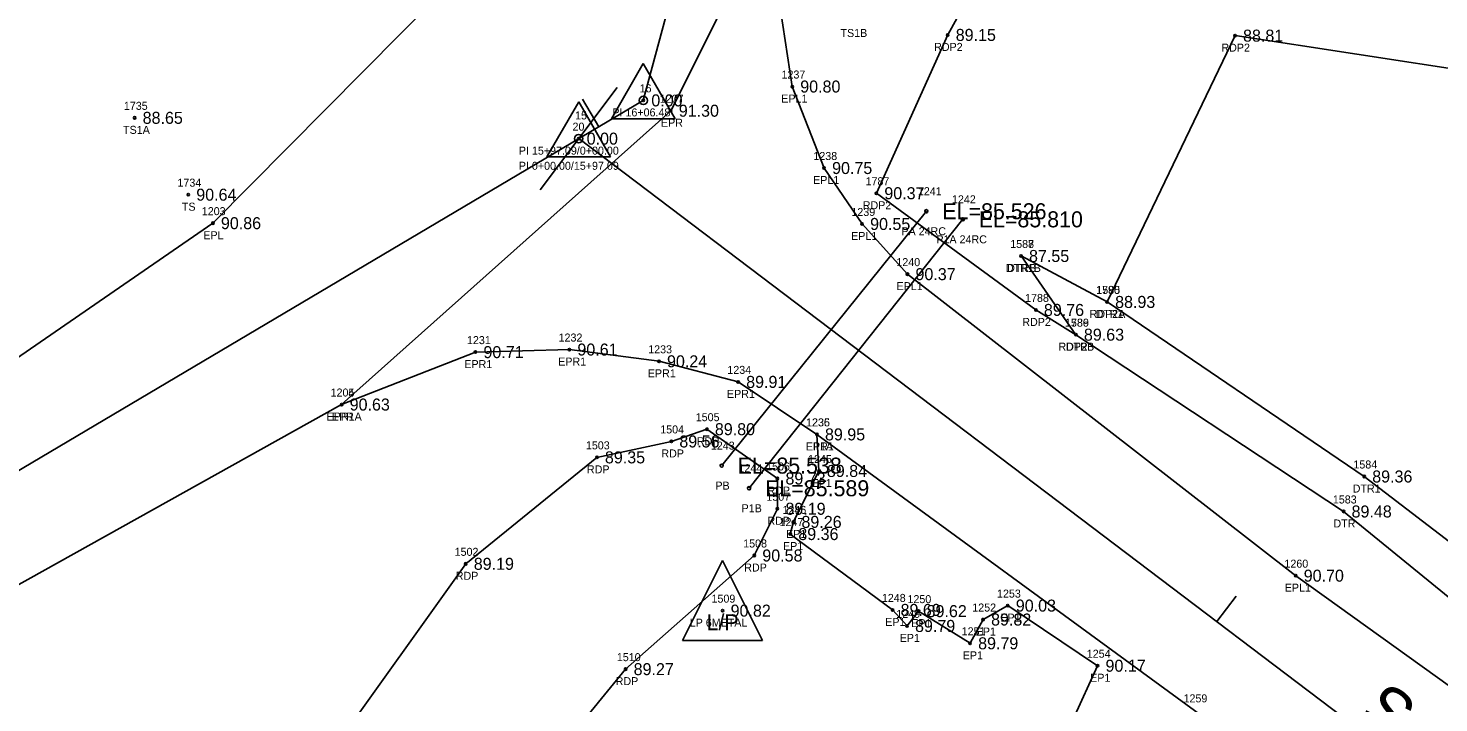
# Model space of a CAD drawing. Extents: x 2529517 to 2532038, y 935000 to 936944.
# Drawn here: x 2531691.2 to 2531867.5, y 936267.3 to 936351.6 of the extents above; entities that cross this region are included whole.
import ezdxf

# ---------------------------------------------------------------- set-up
doc = ezdxf.new("R2010")
doc.units = 0
for name, color, linetype in [('Default', 7, 'Continuous'), ('RD_DTM_BkLn_txCode', 7, 'Continuous'), ('RD_EX_DR_ErosCtrl', 7, 'Continuous'), ('RD_EX_DR_ErosCtrl_txCode', 7, 'Continuous'), ('RD_EX_DR_Pipe', 7, 'Continuous'), ('RD_EX_DR_Pipe_txCode', 7, 'Continuous'), ('RD_EX_H2O', 7, 'Continuous'), ('RD_EX_H2O_txCode', 7, 'Continuous'), ('RD_EX_Road', 7, 'Continuous'), ('RD_EX_Road_txCode', 7, 'Continuous'), ('RD_EX_TX_DR_ErosCtrl_ELEV', 7, 'Continuous'), ('RD_EX_TX_H2O_ELEV', 7, 'Continuous'), ('RD_EX_TX_Misc_ELEV', 7, 'Continuous'), ('RD_EX_TX_Road_ELEV', 7, 'Continuous'), ('RD_EX_TX_UT_ELEV', 7, 'Continuous'), ('RD_EX_UT', 7, 'Continuous'), ('RD_EX_UT_txCode', 7, 'Continuous'), ('RD_HC_Cl', 7, 'Continuous'), ('RD_HC_Data', 7, 'Continuous'), ('RD_HC_Data_Tic', 7, 'Continuous'), ('RD_HC_Survey_ELEV', 7, 'Continuous'), ('RD_HC_txCode', 7, 'Continuous'), ('RD_SMD_Locator', 7, 'Continuous'), ('RD_TX_Pipe_ElevEX', 7, 'Continuous')]:
    doc.layers.add(name, color=color, linetype=linetype)

msp = doc.modelspace()

# ---------------------------------------------------------------- linework, layer by layer
at = {"layer": 'Default'}
for p, q in [((2531768.07, 936342.55), (2531830.33, 936573.34)), ((2530557.05, 935625.34), (2531768.07, 936342.55)), ((2531759.99, 936337.77), (2531999.23, 936156.76))]:
    msp.add_line(p, q, dxfattribs=at)
at = {"layer": 'RD_EX_DR_ErosCtrl'}
for points in [[(2531913.23, 936552.65), (2531879.89, 936486.26), (2531843.11, 936418.02), (2531806.11, 936350.73), (2531797.19, 936330.95), (2531817.13, 936316.37), (2531822.13, 936313.28)], [(2531826.03, 936317.37), (2531842.02, 936350.64), (2531872.46, 936345.98), (2531906.05, 936401.13), (2531944.32, 936458.1), (2531968.34, 936447.83), (2531976.81, 936458.99), (2531957.81, 936476.14), (2531966.51, 936493.14)], [(2531712.5, 936237.97), (2531745.88, 936284.65), (2531762.27, 936297.95), (2531771.57, 936299.94), (2531776.01, 936301.47), (2531784.83, 936295.31), (2531784.83, 936291.53), (2531781.94, 936285.69), (2531765.86, 936271.49), (2531751.65, 936254.14)]]:
    msp.add_lwpolyline(points, dxfattribs=at)
at = {"layer": 'RD_EX_DR_Pipe'}
for p, q in [((2531803.44, 936328.7), (2531777.86, 936296.92)), ((2531807.99, 936327.69), (2531781.29, 936294.09))]:
    msp.add_line(p, q, dxfattribs=at)
at = {"layer": 'RD_EX_H2O'}
for points in [[(2531888.89, 936272.02), (2531858.16, 936295.56), (2531826.03, 936317.37), (2531815.27, 936323.11)], [(2531888.89, 936272.02), (2531887.88, 936268.95), (2531883.72, 936268.22), (2531855.58, 936291.19), (2531822.13, 936313.28), (2531815.27, 936323.11)]]:
    msp.add_lwpolyline(points, dxfattribs=at)
at = {"layer": 'RD_EX_Road'}
for points in [[(2531169.65, 936000.77), (2531208.79, 936024.95), (2531292.04, 936074.02), (2531376.24, 936123.7), (2531460.37, 936174.49), (2531542.92, 936223.44), (2531626.67, 936270.85), (2531672.4, 936298.39), (2531714.28, 936327.21), (2531747.19, 936360.45), (2531761.42, 936377.32), (2531773.11, 936411.11), (2531782.2, 936441.65), (2531803.17, 936514.76), (2531820.28, 936585.8)], [(2531180.82, 935982), (2531220.82, 936004.21), (2531303.54, 936053.39), (2531388.75, 936103.71), (2531472.27, 936152.98), (2531554.79, 936201.9), (2531638.11, 936250.92), (2531683.19, 936278.28), (2531730.37, 936304.55), (2531771.5, 936341.26), (2531788.67, 936375.53), (2531805.57, 936434.84), (2531825.53, 936508.74), (2531844.13, 936579.65)], [(2531788.67, 936375.53), (2531784.05, 936361.55), (2531786.68, 936344.28), (2531790.66, 936334.1), (2531795.41, 936327.11), (2531801.08, 936320.84), (2531849.6, 936283.17), (2531876.01, 936264.22), (2531894.71, 936249.13), (2531930.69, 936221.59), (2532010.91, 936160.51)], [(2531730.37, 936304.55), (2531747.09, 936311.1), (2531758.83, 936311.42), (2531770.03, 936309.95), (2531779.92, 936307.38), (2531789.77, 936300.82), (2531836.93, 936266.34), (2531918.06, 936205.29), (2531926.11, 936199.32), (2531961.6, 936172.59), (2531979.77, 936158.9), (2531999.31, 936144.02)], [(2531789.77, 936300.82), (2531790.01, 936296.25), (2531786.83, 936289.89), (2531786.44, 936288.37), (2531799.22, 936278.89), (2531801.03, 936276.89), (2531802.47, 936278.74), (2531808.91, 936274.72), (2531810.53, 936277.69), (2531813.62, 936279.43), (2531824.83, 936271.92), (2531821.79, 936265.23), (2531839.12, 936251.81), (2531833.01, 936238.75), (2531836.1, 936237.39)]]:
    msp.add_lwpolyline(points, dxfattribs=at)
at = {"layer": 'RD_EX_UT'}
for p, q in [((2531772.98, 936275.08), (2531777.98, 936285.08)), ((2531777.98, 936285.08), (2531782.98, 936275.08)), ((2531772.98, 936275.08), (2531782.98, 936275.08))]:
    msp.add_line(p, q, dxfattribs=at)
at = {"layer": 'RD_HC_Cl'}
for p, q in [((2531768.07, 936342.55), (2531830.33, 936573.34)), ((2530557.05, 935625.34), (2531768.07, 936342.55)), ((2531759.99, 936337.77), (2531999.23, 936156.76))]:
    msp.add_line(p, q, dxfattribs=at)
at = {"layer": 'RD_HC_Data'}
for p, q in [((2531764.1, 936340.26), (2531768.07, 936347.14)), ((2531768.07, 936347.14), (2531772.04, 936340.26)), ((2531756.02, 936335.48), (2531759.99, 936342.36)), ((2531756.02, 936335.48), (2531759.99, 936342.36)), ((2531759.99, 936342.36), (2531763.96, 936335.48)), ((2531759.99, 936342.36), (2531763.96, 936335.48)), ((2531764.1, 936340.26), (2531772.04, 936340.26)), ((2531756.02, 936335.48), (2531763.96, 936335.48)), ((2531756.02, 936335.48), (2531763.96, 936335.48))]:
    msp.add_line(p, q, dxfattribs=at)
for centre in [(2531768.07, 936342.55), (2531759.99, 936337.77), (2531759.99, 936337.77)]:
    msp.add_circle(centre, 0.529, dxfattribs=at)
at = {"layer": 'RD_HC_Data_Tic'}
for p, q in [((2531759.99, 936337.77), (2531764.82, 936344.15)), ((2531762.49, 936339.25), (2531760.46, 936342.69)), ((2531759.99, 936337.77), (2531755.16, 936331.39)), ((2531839.74, 936277.43), (2531842.15, 936280.62))]:
    msp.add_line(p, q, dxfattribs=at)
at = {"layer": 'RD_SMD_Locator'}
for centre, radius in [((2531806.11, 936350.73), 0.15), ((2531842.02, 936350.64), 0.15), ((2531786.68, 936344.28), 0.15), ((2531768.07, 936342.55), 0.15), ((2531704.5, 936340.37), 0.15), ((2531771.5, 936341.26), 0.15), ((2531759.99, 936337.77), 0.15), ((2531759.99, 936337.77), 0.15), ((2531790.66, 936334.1), 0.15), ((2531711.2, 936330.77), 0.15), ((2531797.19, 936330.95), 0.15), ((2531803.44, 936328.7), 0.2), ((2531807.99, 936327.69), 0.2), ((2531714.28, 936327.21), 0.15), ((2531795.41, 936327.11), 0.15), ((2531815.27, 936323.11), 0.15), ((2531815.27, 936323.11), 0.15), ((2531801.08, 936320.84), 0.15), ((2531826.03, 936317.37), 0.15), ((2531826.03, 936317.37), 0.15), ((2531817.13, 936316.37), 0.15), ((2531822.13, 936313.28), 0.15), ((2531822.13, 936313.28), 0.15), ((2531747.09, 936311.1), 0.15), ((2531758.83, 936311.42), 0.15), ((2531770.03, 936309.95), 0.15), ((2531779.92, 936307.38), 0.15), ((2531730.37, 936304.55), 0.15), ((2531730.37, 936304.55), 0.15), ((2531776.01, 936301.47), 0.15), ((2531771.57, 936299.94), 0.15), ((2531789.77, 936300.82), 0.15), ((2531789.77, 936300.82), 0.15), ((2531762.27, 936297.95), 0.15), ((2531777.86, 936296.92), 0.2), ((2531790.01, 936296.25), 0.15), ((2531781.29, 936294.09), 0.2), ((2531784.83, 936295.31), 0.15), ((2531858.16, 936295.56), 0.15), ((2531784.83, 936291.53), 0.15), ((2531855.58, 936291.19), 0.15), ((2531786.83, 936289.89), 0.15), ((2531786.44, 936288.37), 0.15), ((2531781.94, 936285.69), 0.15), ((2531745.88, 936284.65), 0.15), ((2531849.6, 936283.17), 0.15), ((2531777.98, 936278.8), 0.15), ((2531799.22, 936278.89), 0.15), ((2531802.47, 936278.74), 0.15), ((2531813.62, 936279.43), 0.15), ((2531801.03, 936276.89), 0.15), ((2531810.53, 936277.69), 0.15), ((2531808.91, 936274.72), 0.15), ((2531765.86, 936271.49), 0.15), ((2531824.83, 936271.92), 0.15)]:
    msp.add_circle(centre, radius, dxfattribs=at)

# ---------------------------------------------------------------- texts
at = {"layer": 'RD_DTM_BkLn_txCode'}
for s, p in [('TS1B', (2531792.71, 936350.47)), ('1735', (2531703.15, 936341.37)), ('TS1A', (2531703.05, 936338.37)), ('1734', (2531709.85, 936331.77)), ('TS', (2531710.4, 936328.77))]:
    msp.add_text(s, height=1, dxfattribs=at).set_placement(p)
at = {"layer": 'RD_EX_DR_ErosCtrl_txCode'}
for s, p in [('RDP2', (2531804.41, 936348.73)), ('RDP2', (2531840.31, 936348.64)), ('1787', (2531795.84, 936331.95)), ('RDP2', (2531795.49, 936328.95)), ('1790', (2531824.65, 936318.37)), ('1788', (2531815.78, 936317.37)), ('RDP2', (2531815.43, 936314.37)), ('1789', (2531820.78, 936314.28)), ('RDP2A', (2531823.84, 936315.37)), ('RDP2B', (2531819.95, 936311.28)), ('1505', (2531774.62, 936302.47)), ('1504', (2531770.18, 936300.94)), ('1503', (2531760.89, 936298.95)), ('RDP', (2531774.75, 936299.47)), ('RDP', (2531770.32, 936297.94)), ('RDP', (2531761.02, 936295.95)), ('1506', (2531783.42, 936296.31)), ('RDP', (2531783.58, 936293.31)), ('1507', (2531783.45, 936292.53)), ('RDP', (2531783.58, 936289.53)), ('1508', (2531780.55, 936286.69)), ('1502', (2531744.49, 936285.65)), ('RDP', (2531744.63, 936282.65)), ('RDP', (2531780.68, 936283.69)), ('1510', (2531764.76, 936272.49)), ('RDP', (2531764.61, 936269.49))]:
    msp.add_text(s, height=1, dxfattribs=at).set_placement(p)
at = {"layer": 'RD_EX_DR_Pipe_txCode'}
for s, p in [('1241', (2531802.38, 936330.7)), ('1242', (2531806.64, 936329.69)), ('PA 24RC', (2531800.32, 936325.7)), ('P1A 24RC', (2531804.69, 936324.69)), ('1243', (2531776.51, 936298.92)), ('1244', (2531779.95, 936296.09)), ('PB', (2531777.08, 936293.92)), ('P1B', (2531780.35, 936291.09))]:
    msp.add_text(s, height=1, dxfattribs=at).set_placement(p)
at = {"layer": 'RD_EX_H2O_txCode'}
for s, p in [('1587', (2531813.92, 936324.11)), ('1588', (2531813.92, 936324.11)), ('DTR1B', (2531813.37, 936321.11)), ('DTRB', (2531813.53, 936321.11)), ('1585', (2531824.68, 936318.37)), ('1586', (2531820.76, 936314.28)), ('DTR1', (2531824.6, 936315.37)), ('DTR', (2531820.86, 936311.28)), ('1584', (2531856.81, 936296.56)), ('DTR1', (2531856.72, 936293.56)), ('1583', (2531854.24, 936292.19)), ('DTR', (2531854.31, 936289.19))]:
    msp.add_text(s, height=1, dxfattribs=at).set_placement(p)
at = {"layer": 'RD_EX_Road_txCode'}
for s, p in [('1237', (2531785.34, 936345.28)), ('1207', (2531770.12, 936342.26)), ('EPL1', (2531785.31, 936342.28)), ('EPR', (2531770.27, 936339.26)), ('1238', (2531789.32, 936335.1)), ('EPL1', (2531789.29, 936332.1)), ('1203', (2531712.89, 936328.21)), ('1239', (2531794.07, 936328.11)), ('EPL', (2531713.08, 936325.21)), ('EPL1', (2531794.04, 936325.11)), ('1240', (2531799.69, 936321.84)), ('EPL1', (2531799.71, 936318.84)), ('1231', (2531746.03, 936312.1)), ('1232', (2531757.48, 936312.42)), ('1233', (2531768.68, 936310.95)), ('EPR1', (2531745.7, 936309.1)), ('EPR1', (2531757.43, 936309.42)), ('EPR1', (2531768.63, 936307.95)), ('1234', (2531778.57, 936308.38)), ('1204', (2531728.99, 936305.55)), ('1205', (2531728.99, 936305.55)), ('EPR1', (2531778.52, 936305.38)), ('EPR1A', (2531728.49, 936302.55)), ('EPR', (2531729.14, 936302.55)), ('1236', (2531788.4, 936301.82)), ('1235', (2531788.42, 936301.82)), ('EP1A', (2531788.36, 936298.82)), ('EPR1', (2531788.38, 936298.82)), ('1245', (2531788.66, 936297.25)), ('EP1', (2531789.09, 936294.25)), ('1246', (2531785.46, 936290.89)), ('1247', (2531785.1, 936289.37)), ('EP1', (2531785.91, 936287.89)), ('EP1', (2531785.52, 936286.37)), ('1260', (2531848.19, 936284.17)), ('EPL1', (2531848.23, 936281.17)), ('1248', (2531797.88, 936279.89)), ('1250', (2531801.08, 936279.74)), ('1253', (2531812.27, 936280.43)), ('1249', (2531799.69, 936277.89)), ('1252', (2531809.18, 936278.69)), ('EP1', (2531812.69, 936277.43)), ('EP1', (2531798.3, 936276.89)), ('EP1', (2531801.55, 936276.74)), ('1251', (2531807.85, 936275.72)), ('EP1', (2531809.61, 936275.69)), ('EP1', (2531800.11, 936274.89)), ('EP1', (2531807.99, 936272.72)), ('1254', (2531823.49, 936272.92)), ('EP1', (2531823.91, 936269.92)), ('1259', (2531835.58, 936267.34))]:
    msp.add_text(s, height=1, dxfattribs=at).set_placement(p)
at = {"layer": 'RD_EX_TX_DR_ErosCtrl_ELEV'}
for s, p in [('89.15', (2531807.11, 936349.98)), ('88.81', (2531843.02, 936349.89)), ('90.37', (2531798.19, 936330.2)), ('89.76', (2531818.13, 936315.62)), ('88.93', (2531827.03, 936316.62)), ('89.63', (2531823.13, 936312.53)), ('89.80', (2531777.01, 936300.72)), ('89.56', (2531772.57, 936299.19)), ('89.35', (2531763.27, 936297.2)), ('89.73', (2531785.83, 936294.56)), ('89.19', (2531785.83, 936290.78)), ('89.19', (2531746.88, 936283.9)), ('90.58', (2531782.94, 936284.94)), ('89.27', (2531766.86, 936270.74))]:
    msp.add_text(s, height=1.5, dxfattribs=at).set_placement(p)
at = {"layer": 'RD_EX_TX_H2O_ELEV'}
for s, p in [('87.55', (2531816.27, 936322.36)), ('87.55', (2531816.27, 936322.36)), ('88.93', (2531827.03, 936316.62)), ('89.63', (2531823.13, 936312.53)), ('89.36', (2531859.16, 936294.81)), ('89.48', (2531856.58, 936290.44))]:
    msp.add_text(s, height=1.5, dxfattribs=at).set_placement(p)
at = {"layer": 'RD_EX_TX_Misc_ELEV'}
for s, p in [('88.65', (2531705.5, 936339.62)), ('90.64', (2531712.2, 936330.02))]:
    msp.add_text(s, height=1.5, dxfattribs=at).set_placement(p)
at = {"layer": 'RD_EX_TX_Road_ELEV'}
for s, p in [('90.80', (2531787.68, 936343.53)), ('91.30', (2531772.5, 936340.51)), ('90.75', (2531791.66, 936333.35)), ('90.86', (2531715.28, 936326.46)), ('90.55', (2531796.41, 936326.36)), ('90.37', (2531802.08, 936320.09)), ('90.71', (2531748.09, 936310.35)), ('90.61', (2531759.83, 936310.67)), ('90.24', (2531771.03, 936309.2)), ('89.91', (2531780.92, 936306.63)), ('90.63', (2531731.37, 936303.8)), ('90.63', (2531731.37, 936303.8)), ('89.95', (2531790.77, 936300.07)), ('89.95', (2531790.77, 936300.07)), ('89.84', (2531791.01, 936295.5)), ('89.26', (2531787.83, 936289.14)), ('89.36', (2531787.44, 936287.62)), ('90.70', (2531850.6, 936282.42)), ('90.03', (2531814.62, 936278.68)), ('89.69', (2531800.22, 936278.14)), ('89.62', (2531803.47, 936277.99)), ('89.82', (2531811.53, 936276.94)), ('89.79', (2531802.03, 936276.14)), ('89.79', (2531809.91, 936273.97)), ('90.17', (2531825.83, 936271.17))]:
    msp.add_text(s, height=1.5, dxfattribs=at).set_placement(p)
at = {"layer": 'RD_EX_TX_UT_ELEV'}
msp.add_text('90.82', height=1.5, dxfattribs=at).set_placement((2531778.98, 936278.05))
at = {"layer": 'RD_EX_UT'}
msp.add_text('L/P', height=2, dxfattribs=at).set_placement((2531775.97, 936276.36))
at = {"layer": 'RD_EX_UT_txCode'}
for s, p in [('1509', (2531776.59, 936279.8)), ('LP 6METAL', (2531773.87, 936276.8))]:
    msp.add_text(s, height=1, dxfattribs=at).set_placement(p)
at = {"layer": 'RD_HC_Data'}
msp.add_text('S 52%%d 53\' 18" E', height=6, rotation=322.8882, dxfattribs=at).set_placement((2531857.25, 936265.44))
at = {"layer": 'RD_HC_Survey_ELEV'}
for p in [(2531769.07, 936341.8), (2531760.99, 936337.02), (2531760.99, 936337.02)]:
    msp.add_text('0.00', height=1.5, dxfattribs=at).set_placement(p)
at = {"layer": 'RD_HC_txCode'}
for s, p in [('16', (2531767.6, 936343.55)), ('15', (2531759.54, 936340.17)), ('PI 16+06.48', (2531764.2, 936340.55)), ('20', (2531759.22, 936338.77)), ('PI 15+97.09/0+00.00', (2531752.51, 936335.77)), ('PI 0+00.00/15+97.09', (2531752.51, 936333.88))]:
    msp.add_text(s, height=1, dxfattribs=at).set_placement(p)
at = {"layer": 'RD_TX_Pipe_ElevEX'}
for s, p in [('EL=85.526', (2531805.44, 936327.7)), ('EL=85.810', (2531809.99, 936326.69)), ('EL=85.538', (2531779.86, 936295.92)), ('EL=85.589', (2531783.29, 936293.09))]:
    msp.add_text(s, height=2, dxfattribs=at).set_placement(p)

doc.saveas('drawing.dxf')
